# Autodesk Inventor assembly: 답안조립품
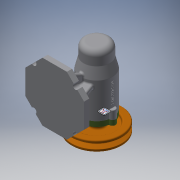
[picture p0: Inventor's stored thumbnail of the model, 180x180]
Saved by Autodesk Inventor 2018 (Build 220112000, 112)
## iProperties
Created: 2019-12
Part Number: 답안조립품
Document SubType Name: Assembly
Designer: Administrator
Author: Administrator
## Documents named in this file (11)
- C:\Users\Administrator\Desktop\491204v1066\답안조립품.iam
- C:\Users\Administrator\Desktop\491204v1066\본체.ipt
- C:\Users\Administrator\Desktop\491204v1066\축.ipt
- C:\Users\Administrator\Desktop\491204v1066\키 5 x 5 x 16.ipt
- C:\Users\Administrator\Desktop\491204v1066\베어링 6004.ipt
- C:\Users\Administrator\Desktop\491204v1066\어댑터슬리브.ipt
- C:\Users\Administrator\Desktop\491204v1066\볼트 M4.ipt
- C:\Users\Administrator\Desktop\491204v1066\베어링 51202.ipt
- C:\Users\Administrator\Desktop\491204v1066\커버.ipt
- C:\Users\Administrator\Desktop\491204v1066\V벨트풀리.ipt
- C:\Users\Administrator\Desktop\491204v1066\멈춤나사 M3.ipt
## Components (1 placed, 1 different names)
1. V벨트풀리:1
